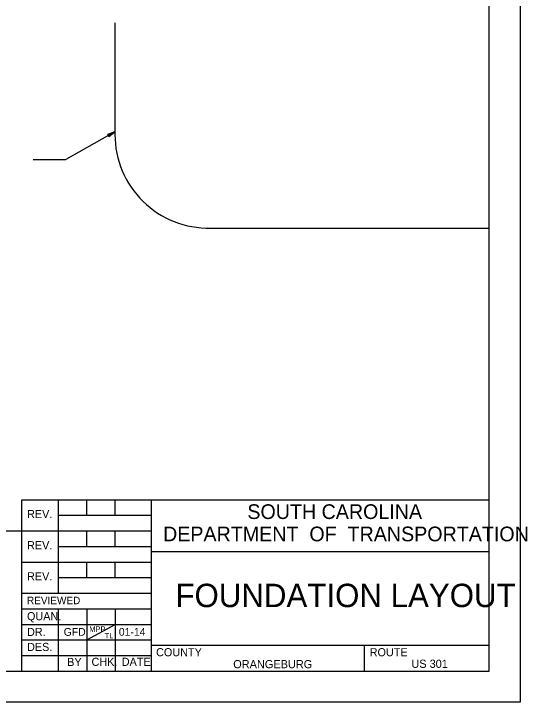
# Model space of a CAD drawing. Extents: x -10371 to -10009, y 1939 to 2167.
# Drawn here: x -10091.9 to -10009.5, y 1939.5 to 2050 of the extents above; entities that cross this region are included whole.
import ezdxf

# ---------------------------------------------------------------- set-up
doc = ezdxf.new("R2010")
doc.units = 0
for name, color, linetype in [('BR_AUTO DIMENSION', 7, 'Continuous'), ('BR_BORDER LINES', 7, 'Continuous'), ('BR_GROUND LINES', 7, 'Continuous'), ('BR_TEXT', 7, 'Continuous'), ('RD_SHT_IplotShp', 7, 'Continuous')]:
    doc.layers.add(name, color=color, linetype=linetype)

msp = doc.modelspace()

# ---------------------------------------------------------------- linework, layer by layer
at = {"layer": 'BR_AUTO DIMENSION'}
for p, q in [((-10075.63, 2031.05), (-10083.48, 2026.57)), ((-10088.73, 2026.57), (-10083.48, 2026.57)), ((-10080.16, 1949.49), (-10075.58, 1951.99))]:
    msp.add_line(p, q, dxfattribs=at)
msp.add_lwpolyline([(-10076.62, 2030.26), (-10075.63, 2031.05), (-10076.81, 2030.59)], close=True, dxfattribs=at)
at = {"layer": 'BR_BORDER LINES'}
for p, q in [((-10015.58, 1944.49), (-10015.58, 2154.49)), ((-10090.58, 1944.49), (-10090.58, 1971.99)), ((-10090.58, 1971.99), (-10015.58, 1971.99)), ((-10084.75, 1971.99), (-10084.75, 1956.99)), ((-10080.16, 1969.49), (-10080.16, 1971.99)), ((-10075.58, 1969.49), (-10075.58, 1971.99)), ((-10069.75, 1944.49), (-10069.75, 1971.99)), ((-10084.75, 1969.49), (-10069.75, 1969.49)), ((-10113.7, 1966.99), (-10090.58, 1966.99)), ((-10090.58, 1966.99), (-10069.75, 1966.99)), ((-10080.16, 1964.49), (-10080.16, 1966.99)), ((-10075.58, 1964.49), (-10075.58, 1966.99)), ((-10084.75, 1964.49), (-10069.75, 1964.49)), ((-10069.75, 1963.66), (-10015.58, 1963.66)), ((-10069.75, 1963.66), (-10069.75, 1963.66)), ((-10015.58, 1963.66), (-10015.58, 1963.66)), ((-10090.58, 1961.99), (-10069.75, 1961.99)), ((-10080.16, 1959.49), (-10080.16, 1961.99)), ((-10075.58, 1959.49), (-10075.58, 1961.99)), ((-10084.75, 1959.49), (-10069.75, 1959.49)), ((-10090.58, 1956.99), (-10069.75, 1956.99)), ((-10090.58, 1954.49), (-10069.75, 1954.49)), ((-10084.75, 1954.49), (-10084.75, 1944.49)), ((-10080.16, 1954.49), (-10080.16, 1944.49)), ((-10075.58, 1954.49), (-10075.58, 1944.49)), ((-10090.58, 1951.99), (-10069.75, 1951.99)), ((-10090.58, 1949.49), (-10069.75, 1949.49)), ((-10069.75, 1948.66), (-10015.58, 1948.66)), ((-10035.58, 1944.49), (-10035.58, 1948.66)), ((-10090.58, 1946.99), (-10069.75, 1946.99)), ((-10352.25, 1944.49), (-10015.58, 1944.49))]:
    msp.add_line(p, q, dxfattribs=at)
at = {"layer": 'BR_GROUND LINES'}
for p, q in [((-10075.63, 2048.54), (-10075.63, 2030.59)), ((-10060.29, 2015.6), (-10015.58, 2015.6))]:
    msp.add_line(p, q, dxfattribs=at)
msp.add_arc((-10060.63, 2030.59), 15, 180, 271.3176, dxfattribs=at)
at = {"layer": 'RD_SHT_IplotShp'}
msp.add_lwpolyline([(-10370.58, 2159.49), (-10010.58, 2159.49), (-10010.58, 1939.49), (-10370.58, 1939.49)], close=True, dxfattribs=at)

# ---------------------------------------------------------------- texts
at = {"layer": 'BR_TEXT'}
for s, height, p in [('SOUTH CAROLINA', 2.3585, (-10054.37, 1968.9)), ('REV.', 1.3, (-10089.73, 1969.05)), ('DEPARTMENT  OF  TRANSPORTATION', 2.3585, (-10067.9, 1965.32)), ('REV.', 1.3, (-10089.73, 1964.05)), ('REV.', 1.3, (-10089.73, 1959.05)), ('FOUNDATION LAYOUT', 3.75, (-10065.92, 1954.76)), ('REVIEWED', 1.2, (-10089.74, 1955.23)), ('QUAN.', 1.3, (-10089.74, 1952.65)), ('DR.', 1.3, (-10089.74, 1950.13)), ('GFD', 1.25, (-10083.85, 1950.15)), ('MPP', 0.875, (-10079.75, 1950.78)), ('01-14', 1.25, (-10075, 1950.16)), ('TL', 0.875, (-10077.28, 1949.74)), ('DES.', 1.3, (-10089.73, 1947.72)), ('COUNTY', 1.3, (-10069.02, 1946.87)), ('ROUTE', 1.3, (-10034.74, 1946.87)), ('BY', 1.3, (-10083.29, 1945.31)), ('CHK.', 1.3, (-10079.38, 1945.33)), ('DATE', 1.3, (-10074.53, 1945.33)), ('ORANGEBURG', 1.313, (-10056.64, 1944.95)), ('US 301', 1.313, (-10028.05, 1945.01))]:
    msp.add_text(s, height=height, dxfattribs=at).set_placement(p)

doc.saveas('drawing.dxf')
